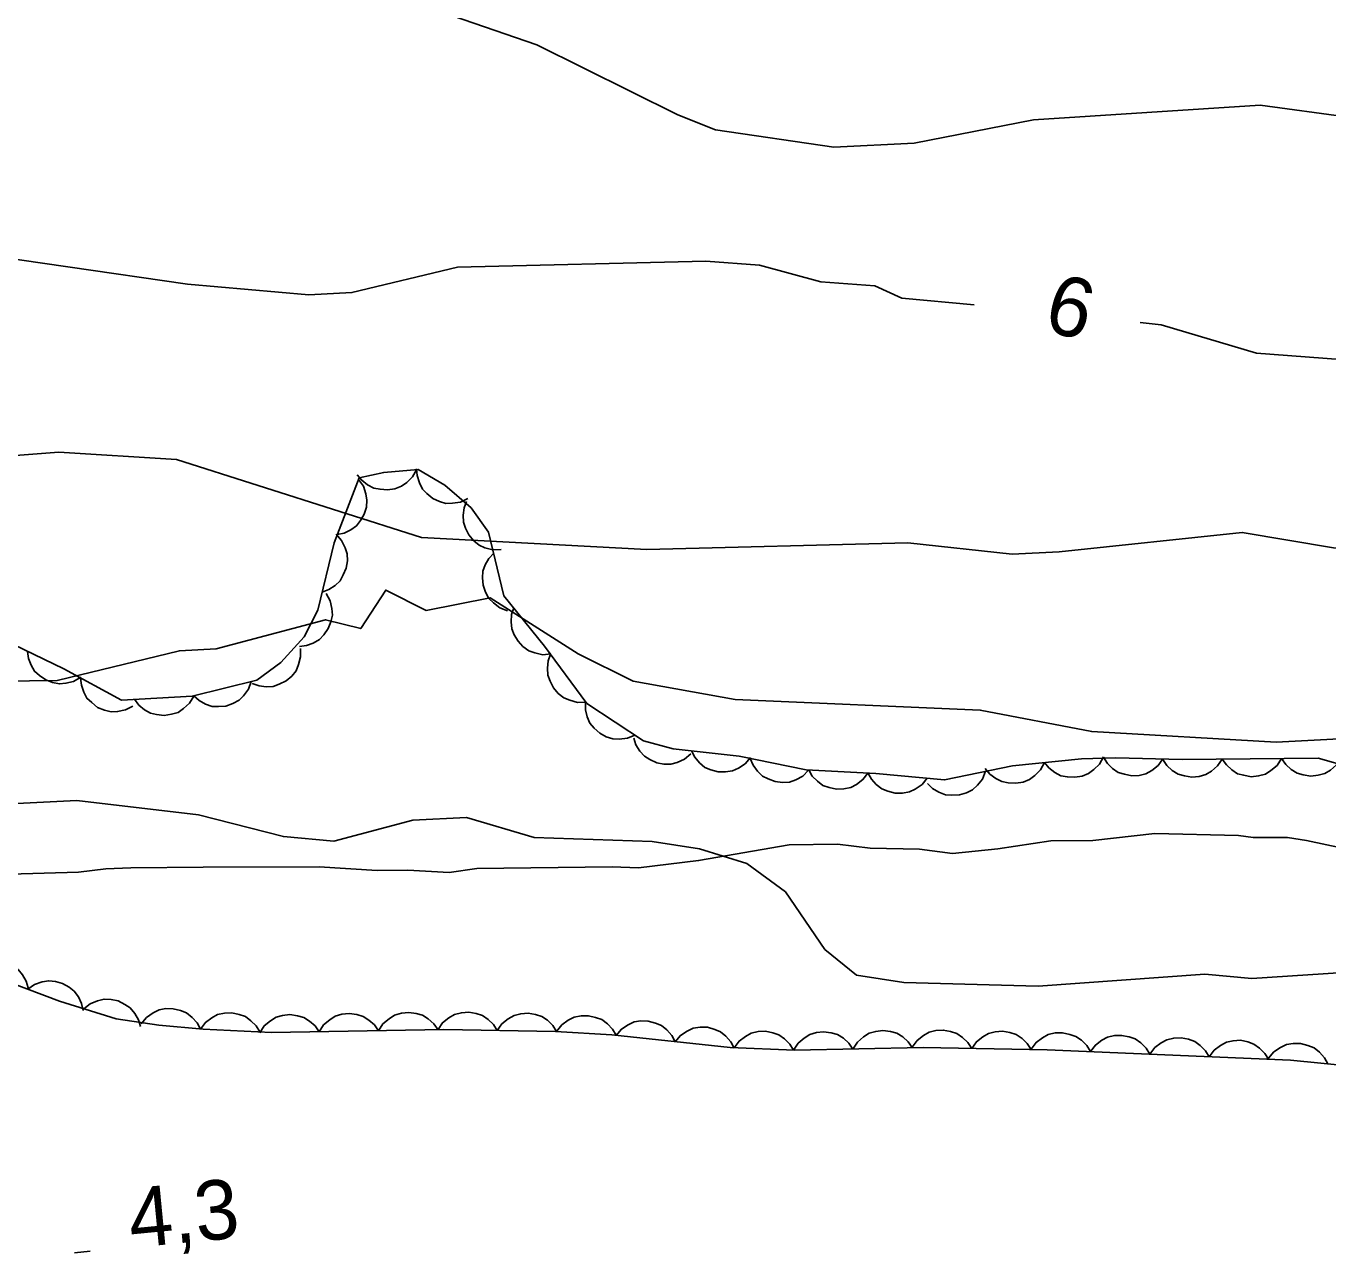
# Model space of a CAD drawing. Extents: x 336540 to 340074, y 5572036 to 5573747.
# Drawn here: x 336980 to 337045.7, y 5572625.5 to 5572687.6 of the extents above; entities that cross this region are included whole.
import ezdxf

# ---------------------------------------------------------------- set-up
doc = ezdxf.new("R2010")
doc.units = 0
for name, color, linetype in [('Niveau 1', 7, 'Continuous'), ('Niveau 2', 7, 'Continuous'), ('Niveau 22', 7, 'Continuous'), ('Niveau 3', 7, 'Continuous'), ('Niveau 44', 7, 'Continuous')]:
    doc.layers.add(name, color=color, linetype=linetype)

msp = doc.modelspace()

# ---------------------------------------------------------------- linework, layer by layer
at = {"layer": 'Niveau 1'}
msp.add_lwpolyline([(337053.17, 5572640.19), (337041.86, 5572639.45), (337039.49, 5572639.67), (337031.06, 5572639.06), (337024.29, 5572639.24), (337021.9, 5572639.61), (337020.3, 5572640.91), (337018.3, 5572643.82), (337016.36, 5572645.25), (337013.96, 5572646), (337011.57, 5572646.37), (337005.61, 5572646.56), (337002.2, 5572647.58), (336999.49, 5572647.44), (336995.49, 5572646.38), (336992.95, 5572646.61), (336988.66, 5572647.72), (336982.52, 5572648.44), (336978.46, 5572648.23)], dxfattribs=at)
at = {"layer": 'Niveau 2'}
for points in [[(336999.39, 5572688.81), (337005.75, 5572686.62), (337012.87, 5572683.08), (337014.78, 5572682.32), (337020.74, 5572681.45), (337024.8, 5572681.65), (337030.83, 5572682.82), (337042.28, 5572683.57), (337046.73, 5572682.96), (337052.72, 5572681.39), (337059.08, 5572679.35), (337065.31, 5572676.77), (337066.73, 5572675.66), (337066.93, 5572675.01), (337065.82, 5572673.59), (337057.65, 5572671.48), (337046.34, 5572670.71), (337042.09, 5572671.03), (337037.28, 5572672.46), (337036.22, 5572672.58)], [(336964.16, 5572676.34), (336968.55, 5572676.38), (336971.12, 5572675.83), (336976.01, 5572676.27), (336988.11, 5572674.52), (336994.24, 5572673.99), (336996.41, 5572674.1), (337001.75, 5572675.38), (337014.28, 5572675.68), (337017, 5572675.48), (337020.09, 5572674.64), (337022.81, 5572674.44), (337024.18, 5572673.82), (337027.83, 5572673.48)], [(337098.26, 5572661), (337089.99, 5572660.92), (337082.87, 5572661.4), (337070.35, 5572661.1), (337065.77, 5572661.36), (337062.08, 5572661.01), (337055.12, 5572661.34), (337050.56, 5572661.1), (337045.98, 5572661.21), (337041.37, 5572661.98), (337032.12, 5572661), (337029.76, 5572660.89), (337024.48, 5572661.45), (337011.3, 5572661.11), (336999.93, 5572661.72), (336987.55, 5572665.66), (336981.61, 5572666.04), (336968.47, 5572665.02)], [(336977.3, 5572654.44), (336981.53, 5572654.5), (336987.7, 5572656), (336989.55, 5572656.1), (336995.08, 5572657.57), (336996.86, 5572657.12), (336998.12, 5572659.07), (337000.16, 5572658.04), (337003.39, 5572658.68), (337007.84, 5572655.84), (337010.62, 5572654.46), (337015.76, 5572653.54), (337028.14, 5572653), (337033.77, 5572651.92), (337043.09, 5572651.39)], [(337043.09, 5572651.39), (337048.5, 5572651.67), (337055.23, 5572652.68), (337060.29, 5572652.94), (337068.08, 5572652.68), (337074.02, 5572651.96), (337080.78, 5572652.46), (337084.19, 5572652.14), (337091.95, 5572652.37)]]:
    msp.add_lwpolyline(points, dxfattribs=at)
at = {"layer": 'Niveau 22'}
msp.add_lwpolyline([(336979.13, 5572644.71), (336982.61, 5572644.81), (336983.98, 5572644.98), (336985.25, 5572645.03), (336988.9, 5572645.07), (336994.76, 5572645.09), (336997.69, 5572644.9), (336999.23, 5572644.92), (337001.33, 5572644.79), (337002.72, 5572645), (337009.56, 5572645.09), (337010.88, 5572645.04), (337013.92, 5572645.4), (337018.49, 5572646.19), (337020.93, 5572646.23), (337022.58, 5572646.03), (337025.08, 5572645.97), (337026.74, 5572645.76), (337029.03, 5572646), (337031.71, 5572646.4), (337033.83, 5572646.41), (337036.96, 5572646.77), (337041.18, 5572646.67), (337041.92, 5572646.57), (337043.65, 5572646.56), (337044.61, 5572646.42), (337047.22, 5572645.86)], dxfattribs=at)
at = {"layer": 'Niveau 3'}
msp.add_line((336982.4, 5572625.59), (336983.2, 5572625.67), dxfattribs=at)
at = {"layer": 'Niveau 44'}
for points in [[(337002.27, 5572663.69), (337001.9, 5572663.51), (337001.49, 5572663.45), (337001.16, 5572663.44), (337000.83, 5572663.54), (337000.49, 5572663.69), (337000.2, 5572663.94), (336999.97, 5572664.17), (336999.82, 5572664.49), (336999.71, 5572664.85), (336999.68, 5572665.2)], [(337048.53, 5572649.63), (337045.2, 5572650.57), (337038.34, 5572650.51), (337034.99, 5572650.6), (337033.25, 5572650.54), (337029.77, 5572650.19), (337026.34, 5572649.48), (337022.86, 5572649.8), (337019.35, 5572649.99), (337015.96, 5572650.67), (337012.63, 5572651.04), (337011.14, 5572651.45), (337008.28, 5572653.33), (337006.14, 5572656.24), (337004.09, 5572658.78), (337003.31, 5572662), (337002.44, 5572663.22), (337001.11, 5572664.37), (336999.76, 5572665.16), (336998.02, 5572665.01), (336996.78, 5572664.73), (336995.51, 5572661.46), (336994.69, 5572658.06), (336994, 5572656.7), (336992.83, 5572655.4), (336991.61, 5572654.52), (336988.35, 5572653.71), (336984.78, 5572653.51), (336981.86, 5572655.08), (336978.84, 5572656.55)], [(336996.75, 5572664.66), (336996.99, 5572664.32), (336997.12, 5572663.93), (336997.17, 5572663.61), (336997.14, 5572663.26), (336997.03, 5572662.9), (336996.84, 5572662.58), (336996.64, 5572662.31), (336996.35, 5572662.11), (336996.02, 5572661.95), (336995.67, 5572661.87)], [(336999.67, 5572665.15), (336999.47, 5572664.79), (336999.18, 5572664.51), (336998.91, 5572664.31), (336998.58, 5572664.19), (336998.21, 5572664.13), (336997.83, 5572664.16), (336997.51, 5572664.22), (336997.2, 5572664.39), (336996.91, 5572664.62), (336996.68, 5572664.89)], [(337003.94, 5572661.11), (337003.53, 5572661.1), (337003.13, 5572661.21), (337002.83, 5572661.34), (337002.56, 5572661.56), (337002.32, 5572661.85), (337002.15, 5572662.19), (337002.04, 5572662.5), (337002.03, 5572662.85), (337002.08, 5572663.22), (337002.2, 5572663.55)], [(336995.61, 5572661.89), (336995.89, 5572661.58), (336996.07, 5572661.21), (336996.17, 5572660.9), (336996.18, 5572660.54), (336996.12, 5572660.18), (336995.97, 5572659.83), (336995.81, 5572659.54), (336995.56, 5572659.3), (336995.25, 5572659.1), (336994.91, 5572658.97)], [(337004.27, 5572658.02), (337003.88, 5572658.17), (337003.56, 5572658.42), (337003.33, 5572658.65), (337003.16, 5572658.96), (337003.04, 5572659.31), (337003.01, 5572659.69), (337003.02, 5572660.02), (337003.14, 5572660.35), (337003.32, 5572660.67), (337003.57, 5572660.94)], [(336995.11, 5572658.89), (336995.32, 5572658.53), (336995.4, 5572658.13), (336995.43, 5572657.8), (336995.35, 5572657.46), (336995.22, 5572657.12), (336994.99, 5572656.81), (336994.77, 5572656.57), (336994.46, 5572656.39), (336994.11, 5572656.26), (336993.76, 5572656.22)], [(337006.46, 5572655.84), (337006.05, 5572655.8), (337005.65, 5572655.89), (337005.34, 5572656), (337005.05, 5572656.21), (337004.8, 5572656.48), (337004.61, 5572656.81), (337004.48, 5572657.11), (337004.45, 5572657.46), (337004.47, 5572657.83), (337004.58, 5572658.17)], [(336993.81, 5572656.11), (336993.82, 5572655.69), (336993.72, 5572655.3), (336993.59, 5572654.99), (336993.37, 5572654.72), (336993.09, 5572654.48), (336992.74, 5572654.31), (336992.44, 5572654.2), (336992.08, 5572654.18), (336991.72, 5572654.23), (336991.38, 5572654.35)], [(336982.73, 5572654.66), (336982.36, 5572654.45), (336981.97, 5572654.36), (336981.64, 5572654.33), (336981.29, 5572654.39), (336980.95, 5572654.53), (336980.64, 5572654.75), (336980.39, 5572654.97), (336980.21, 5572655.27), (336980.08, 5572655.61), (336980.03, 5572655.97)], [(337008.22, 5572653.41), (337007.8, 5572653.39), (337007.41, 5572653.5), (337007.11, 5572653.62), (337006.83, 5572653.84), (337006.59, 5572654.12), (337006.42, 5572654.46), (337006.3, 5572654.77), (337006.28, 5572655.12), (337006.32, 5572655.49), (337006.44, 5572655.83)], [(336985.35, 5572653.2), (336984.98, 5572653.01), (336984.58, 5572652.93), (336984.25, 5572652.92), (336983.91, 5572653), (336983.57, 5572653.14), (336983.27, 5572653.38), (336983.03, 5572653.6), (336982.87, 5572653.91), (336982.75, 5572654.27), (336982.71, 5572654.62)], [(336991.33, 5572654.45), (336991.19, 5572654.06), (336990.94, 5572653.73), (336990.71, 5572653.5), (336990.4, 5572653.33), (336990.05, 5572653.21), (336989.67, 5572653.18), (336989.35, 5572653.19), (336989.01, 5572653.31), (336988.69, 5572653.49), (336988.42, 5572653.73)], [(336988.42, 5572653.71), (336988.21, 5572653.36), (336987.91, 5572653.08), (336987.63, 5572652.89), (336987.3, 5572652.79), (336986.93, 5572652.73), (336986.55, 5572652.78), (336986.24, 5572652.85), (336985.93, 5572653.02), (336985.65, 5572653.26), (336985.43, 5572653.55)], [(337010.7, 5572651.74), (337010.32, 5572651.58), (337009.91, 5572651.54), (337009.58, 5572651.55), (337009.25, 5572651.66), (337008.93, 5572651.83), (337008.65, 5572652.09), (337008.43, 5572652.34), (337008.29, 5572652.66), (337008.2, 5572653.02), (337008.2, 5572653.38)], [(337013.53, 5572650.79), (337013.21, 5572650.52), (337012.84, 5572650.36), (337012.52, 5572650.27), (337012.17, 5572650.27), (337011.81, 5572650.34), (337011.46, 5572650.5), (337011.18, 5572650.67), (337010.95, 5572650.93), (337010.75, 5572651.25), (337010.64, 5572651.59)], [(337016.54, 5572650.61), (337016.27, 5572650.29), (337015.93, 5572650.07), (337015.63, 5572649.93), (337015.28, 5572649.88), (337014.91, 5572649.89), (337014.54, 5572649.99), (337014.24, 5572650.11), (337013.97, 5572650.34), (337013.73, 5572650.62), (337013.56, 5572650.94)], [(337019.47, 5572649.97), (337019.18, 5572649.67), (337018.82, 5572649.48), (337018.51, 5572649.37), (337018.15, 5572649.35), (337017.79, 5572649.39), (337017.43, 5572649.53), (337017.14, 5572649.67), (337016.89, 5572649.92), (337016.67, 5572650.22), (337016.53, 5572650.56)], [(337031.38, 5572650.35), (337031.18, 5572649.98), (337030.89, 5572649.7), (337030.62, 5572649.5), (337030.3, 5572649.37), (337029.93, 5572649.31), (337029.55, 5572649.33), (337029.23, 5572649.39), (337028.92, 5572649.55), (337028.62, 5572649.77), (337028.39, 5572650.05)], [(337034.36, 5572650.65), (337034.16, 5572650.28), (337033.87, 5572650), (337033.61, 5572649.8), (337033.28, 5572649.67), (337032.92, 5572649.61), (337032.54, 5572649.63), (337032.21, 5572649.69), (337031.9, 5572649.85), (337031.61, 5572650.08), (337031.38, 5572650.35)], [(337037.36, 5572650.54), (337037.12, 5572650.2), (337036.8, 5572649.95), (337036.51, 5572649.78), (337036.17, 5572649.7), (337035.8, 5572649.68), (337035.42, 5572649.76), (337035.11, 5572649.85), (337034.82, 5572650.05), (337034.56, 5572650.31), (337034.36, 5572650.62)], [(337040.36, 5572650.53), (337040.13, 5572650.18), (337039.82, 5572649.92), (337039.54, 5572649.75), (337039.2, 5572649.65), (337038.83, 5572649.62), (337038.45, 5572649.68), (337038.14, 5572649.76), (337037.84, 5572649.96), (337037.57, 5572650.21), (337037.36, 5572650.5)], [(337043.36, 5572650.55), (337043.13, 5572650.21), (337042.82, 5572649.95), (337042.54, 5572649.77), (337042.2, 5572649.68), (337041.83, 5572649.64), (337041.45, 5572649.71), (337041.14, 5572649.79), (337040.84, 5572649.98), (337040.57, 5572650.23), (337040.36, 5572650.53)], [(337046.36, 5572650.58), (337046.13, 5572650.23), (337045.82, 5572649.97), (337045.54, 5572649.8), (337045.2, 5572649.71), (337044.83, 5572649.67), (337044.45, 5572649.73), (337044.14, 5572649.82), (337043.84, 5572650.01), (337043.57, 5572650.26), (337043.36, 5572650.55)], [(337022.47, 5572649.82), (337022.22, 5572649.49), (337021.89, 5572649.25), (337021.6, 5572649.09), (337021.25, 5572649.02), (337020.89, 5572649.01), (337020.51, 5572649.09), (337020.2, 5572649.2), (337019.92, 5572649.41), (337019.66, 5572649.67), (337019.48, 5572649.98)], [(337025.46, 5572649.56), (337025.2, 5572649.24), (337024.86, 5572649.01), (337024.56, 5572648.87), (337024.21, 5572648.81), (337023.84, 5572648.81), (337023.47, 5572648.91), (337023.17, 5572649.02), (337022.89, 5572649.24), (337022.65, 5572649.52), (337022.47, 5572649.84)], [(337028.41, 5572649.91), (337028.25, 5572649.52), (337028, 5572649.21), (337027.75, 5572648.98), (337027.44, 5572648.83), (337027.09, 5572648.72), (337026.7, 5572648.71), (337026.38, 5572648.73), (337026.05, 5572648.86), (337025.73, 5572649.05), (337025.47, 5572649.3)], [(336977.2, 5572639.85), (336977.52, 5572640.11), (336977.9, 5572640.26), (336978.22, 5572640.34), (336978.57, 5572640.33), (336978.93, 5572640.25), (336979.27, 5572640.08), (336979.55, 5572639.9), (336979.77, 5572639.63), (336979.96, 5572639.31), (336980.06, 5572638.97)], [(336979.11, 5572639.26), (336981.65, 5572638.29), (336984.51, 5572637.4), (336986.66, 5572637.08), (336988.9, 5572636.88), (336992.35, 5572636.71), (337001.06, 5572636.86), (337006.69, 5572636.77), (337009.53, 5572636.59), (337015.52, 5572635.95), (337018.76, 5572635.82), (337025.26, 5572635.96), (337031.52, 5572635.84), (337043.81, 5572635.31), (337046.87, 5572635.01)], [(336980.04, 5572638.9), (336980.38, 5572639.14), (336980.77, 5572639.27), (336981.1, 5572639.33), (336981.45, 5572639.29), (336981.8, 5572639.19), (336982.13, 5572639), (336982.39, 5572638.8), (336982.6, 5572638.52), (336982.76, 5572638.18), (336982.84, 5572637.83)], [(336982.87, 5572637.91), (336983.2, 5572638.17), (336983.57, 5572638.32), (336983.9, 5572638.4), (336984.25, 5572638.39), (336984.61, 5572638.31), (336984.95, 5572638.13), (336985.22, 5572637.96), (336985.45, 5572637.68), (336985.63, 5572637.36), (336985.74, 5572637.02)], [(336985.77, 5572637.16), (336986.04, 5572637.48), (336986.37, 5572637.71), (336986.67, 5572637.86), (336987.02, 5572637.92), (336987.39, 5572637.91), (336987.76, 5572637.82), (336988.06, 5572637.7), (336988.34, 5572637.48), (336988.59, 5572637.21), (336988.76, 5572636.89)], [(336988.76, 5572636.89), (336989.01, 5572637.22), (336989.34, 5572637.46), (336989.63, 5572637.62), (336989.97, 5572637.69), (336990.34, 5572637.71), (336990.72, 5572637.62), (336991.03, 5572637.52), (336991.31, 5572637.31), (336991.57, 5572637.05), (336991.76, 5572636.74)], [(336991.76, 5572636.7), (336991.98, 5572637.05), (336992.3, 5572637.31), (336992.58, 5572637.49), (336992.91, 5572637.58), (336993.28, 5572637.62), (336993.66, 5572637.56), (336993.98, 5572637.48), (336994.27, 5572637.29), (336994.55, 5572637.05), (336994.76, 5572636.75)], [(336994.76, 5572636.75), (336994.98, 5572637.1), (336995.3, 5572637.36), (336995.57, 5572637.54), (336995.91, 5572637.64), (336996.28, 5572637.67), (336996.66, 5572637.62), (336996.98, 5572637.53), (336997.27, 5572637.34), (336997.55, 5572637.1), (336997.76, 5572636.8)], [(336997.76, 5572636.8), (336997.98, 5572637.15), (336998.3, 5572637.41), (336998.57, 5572637.59), (336998.91, 5572637.69), (336999.28, 5572637.73), (336999.66, 5572637.67), (336999.97, 5572637.59), (337000.27, 5572637.4), (337000.55, 5572637.15), (337000.76, 5572636.85)], [(337000.76, 5572636.86), (337000.99, 5572637.21), (337001.31, 5572637.46), (337001.6, 5572637.63), (337001.94, 5572637.71), (337002.31, 5572637.74), (337002.69, 5572637.67), (337003, 5572637.57), (337003.29, 5572637.37), (337003.56, 5572637.12), (337003.75, 5572636.82)], [(337003.75, 5572636.82), (337003.99, 5572637.16), (337004.31, 5572637.41), (337004.6, 5572637.58), (337004.94, 5572637.66), (337005.31, 5572637.69), (337005.69, 5572637.62), (337006, 5572637.53), (337006.29, 5572637.33), (337006.56, 5572637.07), (337006.75, 5572636.77)], [(337006.75, 5572636.77), (337007.01, 5572637.1), (337007.34, 5572637.33), (337007.63, 5572637.49), (337007.98, 5572637.55), (337008.35, 5572637.56), (337008.72, 5572637.47), (337009.03, 5572637.37), (337009.31, 5572637.16), (337009.57, 5572636.89), (337009.75, 5572636.58)], [(337009.75, 5572636.57), (337010.02, 5572636.89), (337010.36, 5572637.11), (337010.66, 5572637.25), (337011, 5572637.3), (337011.37, 5572637.29), (337011.74, 5572637.19), (337012.05, 5572637.07), (337012.32, 5572636.85), (337012.56, 5572636.57), (337012.73, 5572636.25)], [(337012.73, 5572636.25), (337013, 5572636.57), (337013.34, 5572636.79), (337013.64, 5572636.93), (337013.99, 5572636.98), (337014.36, 5572636.98), (337014.73, 5572636.87), (337015.03, 5572636.75), (337015.3, 5572636.53), (337015.54, 5572636.25), (337015.71, 5572635.93)], [(337015.71, 5572635.94), (337015.96, 5572636.28), (337016.29, 5572636.52), (337016.58, 5572636.68), (337016.92, 5572636.76), (337017.29, 5572636.78), (337017.66, 5572636.7), (337017.97, 5572636.6), (337018.26, 5572636.39), (337018.52, 5572636.13), (337018.71, 5572635.82)], [(337018.71, 5572635.82), (337018.94, 5572636.17), (337019.25, 5572636.43), (337019.53, 5572636.61), (337019.87, 5572636.71), (337020.23, 5572636.75), (337020.61, 5572636.69), (337020.93, 5572636.61), (337021.23, 5572636.42), (337021.5, 5572636.18), (337021.71, 5572635.88)], [(337021.71, 5572635.88), (337021.94, 5572636.23), (337022.25, 5572636.5), (337022.53, 5572636.68), (337022.86, 5572636.77), (337023.23, 5572636.81), (337023.61, 5572636.76), (337023.93, 5572636.68), (337024.23, 5572636.49), (337024.5, 5572636.24), (337024.71, 5572635.95)], [(337024.71, 5572635.97), (337024.95, 5572636.31), (337025.27, 5572636.56), (337025.56, 5572636.73), (337025.9, 5572636.81), (337026.27, 5572636.84), (337026.64, 5572636.77), (337026.96, 5572636.67), (337027.25, 5572636.47), (337027.51, 5572636.21), (337027.71, 5572635.91)], [(337027.71, 5572635.91), (337027.95, 5572636.25), (337028.27, 5572636.5), (337028.56, 5572636.67), (337028.9, 5572636.75), (337029.27, 5572636.78), (337029.64, 5572636.71), (337029.96, 5572636.61), (337030.25, 5572636.41), (337030.51, 5572636.16), (337030.71, 5572635.86)], [(337030.71, 5572635.87), (337030.96, 5572636.21), (337031.29, 5572636.45), (337031.57, 5572636.61), (337031.92, 5572636.69), (337032.29, 5572636.7), (337032.66, 5572636.62), (337032.97, 5572636.52), (337033.26, 5572636.32), (337033.52, 5572636.05), (337033.71, 5572635.75)], [(337033.71, 5572635.75), (337033.96, 5572636.08), (337034.28, 5572636.32), (337034.57, 5572636.48), (337034.92, 5572636.56), (337035.28, 5572636.57), (337035.66, 5572636.49), (337035.97, 5572636.39), (337036.25, 5572636.19), (337036.52, 5572635.92), (337036.7, 5572635.62)], [(337036.7, 5572635.62), (337036.95, 5572635.95), (337037.28, 5572636.19), (337037.57, 5572636.35), (337037.91, 5572636.43), (337038.28, 5572636.45), (337038.66, 5572636.37), (337038.97, 5572636.26), (337039.25, 5572636.06), (337039.51, 5572635.79), (337039.7, 5572635.49)], [(337039.7, 5572635.49), (337039.95, 5572635.82), (337040.28, 5572636.06), (337040.57, 5572636.22), (337040.91, 5572636.3), (337041.28, 5572636.32), (337041.65, 5572636.24), (337041.96, 5572636.13), (337042.25, 5572635.93), (337042.51, 5572635.66), (337042.7, 5572635.36)], [(337042.7, 5572635.42), (337042.97, 5572635.74), (337043.31, 5572635.96), (337043.61, 5572636.11), (337043.95, 5572636.16), (337044.32, 5572636.16), (337044.69, 5572636.06), (337045, 5572635.94), (337045.27, 5572635.72), (337045.52, 5572635.44), (337045.69, 5572635.13)]]:
    msp.add_lwpolyline(points, dxfattribs=at)

# ---------------------------------------------------------------- texts
at = {"layer": 'Niveau 2'}
msp.add_text('6', height=3, rotation=344.86417, dxfattribs=at).set_placement((337031.24, 5572672.23))
at = {"layer": 'Niveau 3'}
msp.add_text('4,3    ', height=3, rotation=5.5424, dxfattribs=at).set_placement((336985.27, 5572625.83))

doc.saveas('drawing.dxf')
